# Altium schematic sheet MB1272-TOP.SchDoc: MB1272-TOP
size A4; CompanyName: STMicroelectronics; DocumentNumber: MB1272; Revision: B-01; SheetNumber: 2; SheetTotal: 15; Project: STM32MP15-DISCO PI
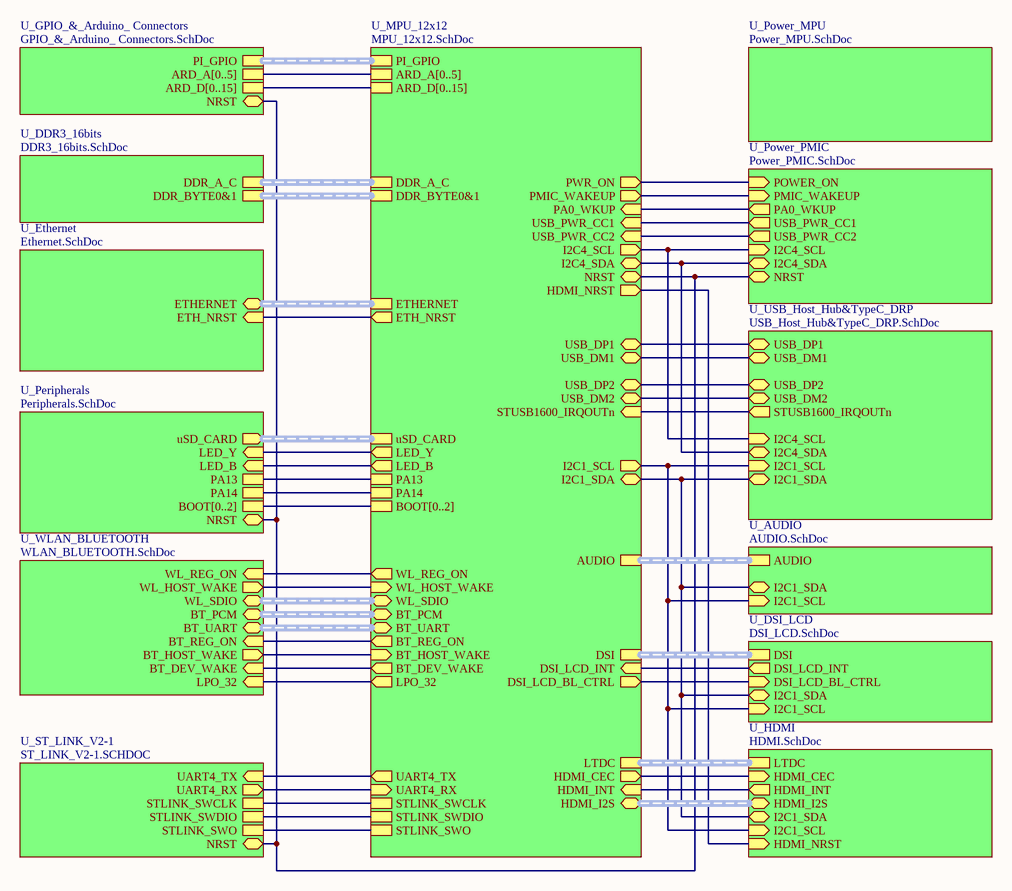
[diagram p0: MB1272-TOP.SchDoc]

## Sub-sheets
U_AUDIO = AUDIO.SchDoc: I2C1_SCL (in), I2C1_SDA (bidir), AUDIO (harness AUDIO)
U_DDR3_16bits = DDR3_16bits.SchDoc: DDR_A_C (harness DDR_A_C), DDR_BYTE0&1 (harness DDR_BYTE_0&1)
U_DSI_LCD = DSI_LCD.SchDoc: DSI (harness DSI), I2C1_SDA (bidir), I2C1_SCL (in), DSI_LCD_BL_CTRL (in), DSI_LCD_INT (out)
U_Ethernet = Ethernet.SchDoc: ETHERNET (harness ETHERNET), ETH_NRST (in)
U_GPIO_&_Arduino_ Connectors = GPIO_&_Arduino_ Connectors.SchDoc: NRST (bidir), ARD_A[0..5], ARD_D[0..15], PI_GPIO (harness PI_GPIO)
U_HDMI = HDMI.SchDoc: LTDC (harness LTDC), HDMI_CEC (in), I2C1_SDA (bidir), HDMI_INT (out), I2C1_SCL (in), HDMI_I2S (harness HDMI_I2S), HDMI_NRST (in)
U_MPU_12x12 = MPU_12x12.SchDoc: DDR_BYTE0&1 (harness DDR_BYTE_0&1), DDR_A_C (harness DDR_A_C), STLINK_SWDIO, STLINK_SWCLK, STLINK_SWO, UART4_TX (out), UART4_RX (in), PA13, PA14, PI_GPIO (harness PI_GPIO), ETHERNET (harness ETHERNET), AUDIO (harness AUDIO), PMIC_WAKEUP (out), PA0_WKUP (in), NRST (bidir), PWR_ON (out), I2C4_SCL (out), I2C4_SDA (bidir), DSI (harness DSI), LTDC (harness LTDC), HDMI_CEC (out), uSD_CARD (harness uSD_CARD), BOOT[0..2], ARD_A[0..5], ARD_D[0..15], I2C1_SDA (bidir), I2C1_SCL (out), USB_DM1 (bidir), USB_DM2 (bidir), USB_DP2 (bidir), USB_DP1 (bidir), DSI_LCD_BL_CTRL (out), DSI_LCD_INT (in), HDMI_INT (in), WL_SDIO (harness WLAN_SDIO), BT_PCM (harness BT_PCM), BT_UART (harness BT_UART), BT_REG_ON (out), BT_HOST_WAKE (in), WL_REG_ON (out), BT_DEV_WAKE (out), WL_HOST_WAKE (in), HDMI_I2S (harness HDMI_I2S), STUSB1600_IRQOUTn (in), LPO_32 (out), USB_PWR_CC1 (in), USB_PWR_CC2 (in), LED_Y (out), LED_B (out), HDMI_NRST (out), ETH_NRST (out)
U_Peripherals = Peripherals.SchDoc: BOOT[0..2], PA13, PA14, NRST (bidir), uSD_CARD (harness uSD_CARD), LED_B (in), LED_Y (in)
U_Power_MPU = Power_MPU.SchDoc: no entries
U_Power_PMIC = Power_PMIC.SchDoc: I2C4_SDA (bidir), I2C4_SCL (in), PA0_WKUP (out), NRST (bidir), POWER_ON (in), PMIC_WAKEUP (in), USB_PWR_CC1 (out), USB_PWR_CC2 (out)
U_ST_LINK_V2-1 = ST_LINK_V2-1.SCHDOC: NRST (bidir), STLINK_SWO, STLINK_SWDIO, STLINK_SWCLK, UART4_RX (out), UART4_TX (in)
U_USB_Host_Hub&TypeC_DRP = USB_Host_Hub&TypeC_DRP.SchDoc: USB_DP1 (bidir), USB_DM1 (bidir), I2C1_SDA (bidir), I2C1_SCL (in), STUSB1600_IRQOUTn (out), I2C4_SCL (in), I2C4_SDA (bidir), USB_DM2 (bidir), USB_DP2 (bidir)
U_WLAN_BLUETOOTH = WLAN_BLUETOOTH.SchDoc: WL_SDIO (harness WLAN_SDIO), BT_UART (harness BT_UART), BT_PCM (harness BT_PCM), BT_REG_ON (in), BT_HOST_WAKE (out), WL_REG_ON (in), BT_DEV_WAKE (in), WL_HOST_WAKE (out), LPO_32 (in)

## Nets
(unnamed): sheet U_Power_PMIC/I2C4_SDA, sheet U_MPU_12x12/I2C4_SDA, sheet U_USB_Host_Hub&TypeC_DRP/I2C4_SDA
(unnamed): sheet U_Power_PMIC/I2C4_SCL, sheet U_MPU_12x12/I2C4_SCL, sheet U_USB_Host_Hub&TypeC_DRP/I2C4_SCL  [a separate net that carries the same name]
(unnamed): sheet U_Power_PMIC/PA0_WKUP, sheet U_MPU_12x12/PA0_WKUP  [a separate net that carries the same name]
(unnamed): sheet U_Power_PMIC/NRST, sheet U_MPU_12x12/NRST, sheet U_Peripherals/NRST, sheet U_ST_LINK_V2-1/NRST, sheet U_GPIO_&_Arduino_ Connectors/NRST  [a separate net that carries the same name]
(unnamed): sheet U_Power_PMIC/POWER_ON, sheet U_MPU_12x12/PWR_ON  [a separate net that carries the same name]
(unnamed): sheet U_Power_PMIC/PMIC_WAKEUP, sheet U_MPU_12x12/PMIC_WAKEUP  [a separate net that carries the same name]
(unnamed): sheet U_Power_PMIC/USB_PWR_CC1, sheet U_MPU_12x12/USB_PWR_CC1  [a separate net that carries the same name]
(unnamed): sheet U_Power_PMIC/USB_PWR_CC2, sheet U_MPU_12x12/USB_PWR_CC2  [a separate net that carries the same name]
(unnamed): sheet U_MPU_12x12/STLINK_SWDIO, sheet U_ST_LINK_V2-1/STLINK_SWDIO  [a separate net that carries the same name]
(unnamed): sheet U_MPU_12x12/STLINK_SWCLK, sheet U_ST_LINK_V2-1/STLINK_SWCLK  [a separate net that carries the same name]
(unnamed): sheet U_MPU_12x12/STLINK_SWO, sheet U_ST_LINK_V2-1/STLINK_SWO  [a separate net that carries the same name]
(unnamed): sheet U_MPU_12x12/UART4_TX, sheet U_ST_LINK_V2-1/UART4_TX  [a separate net that carries the same name]
(unnamed): sheet U_MPU_12x12/UART4_RX, sheet U_ST_LINK_V2-1/UART4_RX  [a separate net that carries the same name]
(unnamed): sheet U_MPU_12x12/PA13, sheet U_Peripherals/PA13  [a separate net that carries the same name]
(unnamed): sheet U_MPU_12x12/PA14, sheet U_Peripherals/PA14  [a separate net that carries the same name]
(unnamed): sheet U_MPU_12x12/HDMI_CEC, sheet U_HDMI/HDMI_CEC  [a separate net that carries the same name]
(unnamed): sheet U_MPU_12x12/I2C1_SDA, sheet U_DSI_LCD/I2C1_SDA, sheet U_HDMI/I2C1_SDA, sheet U_USB_Host_Hub&TypeC_DRP/I2C1_SDA, sheet U_AUDIO/I2C1_SDA  [a separate net that carries the same name]
(unnamed): sheet U_MPU_12x12/I2C1_SCL, sheet U_DSI_LCD/I2C1_SCL, sheet U_HDMI/I2C1_SCL, sheet U_USB_Host_Hub&TypeC_DRP/I2C1_SCL, sheet U_AUDIO/I2C1_SCL  [a separate net that carries the same name]
(unnamed): sheet U_MPU_12x12/USB_DM1, sheet U_USB_Host_Hub&TypeC_DRP/USB_DM1  [a separate net that carries the same name]
(unnamed): sheet U_MPU_12x12/USB_DM2, sheet U_USB_Host_Hub&TypeC_DRP/USB_DM2  [a separate net that carries the same name]
(unnamed): sheet U_MPU_12x12/USB_DP2, sheet U_USB_Host_Hub&TypeC_DRP/USB_DP2  [a separate net that carries the same name]
(unnamed): sheet U_MPU_12x12/USB_DP1, sheet U_USB_Host_Hub&TypeC_DRP/USB_DP1  [a separate net that carries the same name]
(unnamed): sheet U_MPU_12x12/DSI_LCD_BL_CTRL, sheet U_DSI_LCD/DSI_LCD_BL_CTRL  [a separate net that carries the same name]
(unnamed): sheet U_MPU_12x12/DSI_LCD_INT, sheet U_DSI_LCD/DSI_LCD_INT  [a separate net that carries the same name]
(unnamed): sheet U_MPU_12x12/HDMI_INT, sheet U_HDMI/HDMI_INT  [a separate net that carries the same name]
(unnamed): sheet U_MPU_12x12/BT_REG_ON, sheet U_WLAN_BLUETOOTH/BT_REG_ON  [a separate net that carries the same name]
(unnamed): sheet U_MPU_12x12/BT_HOST_WAKE, sheet U_WLAN_BLUETOOTH/BT_HOST_WAKE  [a separate net that carries the same name]
(unnamed): sheet U_MPU_12x12/WL_REG_ON, sheet U_WLAN_BLUETOOTH/WL_REG_ON  [a separate net that carries the same name]
(unnamed): sheet U_MPU_12x12/BT_DEV_WAKE, sheet U_WLAN_BLUETOOTH/BT_DEV_WAKE  [a separate net that carries the same name]
(unnamed): sheet U_MPU_12x12/WL_HOST_WAKE, sheet U_WLAN_BLUETOOTH/WL_HOST_WAKE  [a separate net that carries the same name]
(unnamed): sheet U_MPU_12x12/STUSB1600_IRQOUTn, sheet U_USB_Host_Hub&TypeC_DRP/STUSB1600_IRQOUTn  [a separate net that carries the same name]
(unnamed): sheet U_MPU_12x12/LPO_32, sheet U_WLAN_BLUETOOTH/LPO_32  [a separate net that carries the same name]
(unnamed): sheet U_MPU_12x12/LED_Y, sheet U_Peripherals/LED_Y  [a separate net that carries the same name]
(unnamed): sheet U_MPU_12x12/LED_B, sheet U_Peripherals/LED_B  [a separate net that carries the same name]
(unnamed): sheet U_MPU_12x12/HDMI_NRST, sheet U_HDMI/HDMI_NRST  [a separate net that carries the same name]
(unnamed): sheet U_MPU_12x12/ETH_NRST, sheet U_Ethernet/ETH_NRST  [a separate net that carries the same name]

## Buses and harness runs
bus sheet U_GPIO_&_Arduino_ Connectors/ARD_A[0..5] = sheet U_MPU_12x12/ARD_A[0..5]
bus sheet U_GPIO_&_Arduino_ Connectors/ARD_D[0..15] = sheet U_MPU_12x12/ARD_D[0..15]
bus sheet U_MPU_12x12/BOOT[0..2] = sheet U_Peripherals/BOOT[0..2]
harness sheet U_AUDIO/AUDIO = sheet U_MPU_12x12/AUDIO
harness sheet U_DDR3_16bits/DDR_A_C = sheet U_MPU_12x12/DDR_A_C
harness sheet U_DDR3_16bits/DDR_BYTE0&1 = sheet U_MPU_12x12/DDR_BYTE0&1
harness sheet U_DSI_LCD/DSI = sheet U_MPU_12x12/DSI
harness sheet U_Ethernet/ETHERNET = sheet U_MPU_12x12/ETHERNET
harness sheet U_GPIO_&_Arduino_ Connectors/PI_GPIO = sheet U_MPU_12x12/PI_GPIO
harness sheet U_HDMI/HDMI_I2S = sheet U_MPU_12x12/HDMI_I2S
harness sheet U_HDMI/LTDC = sheet U_MPU_12x12/LTDC
harness sheet U_MPU_12x12/BT_PCM = sheet U_WLAN_BLUETOOTH/BT_PCM
harness sheet U_MPU_12x12/BT_UART = sheet U_WLAN_BLUETOOTH/BT_UART
harness sheet U_MPU_12x12/uSD_CARD = sheet U_Peripherals/uSD_CARD
harness sheet U_MPU_12x12/WL_SDIO = sheet U_WLAN_BLUETOOTH/WL_SDIO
